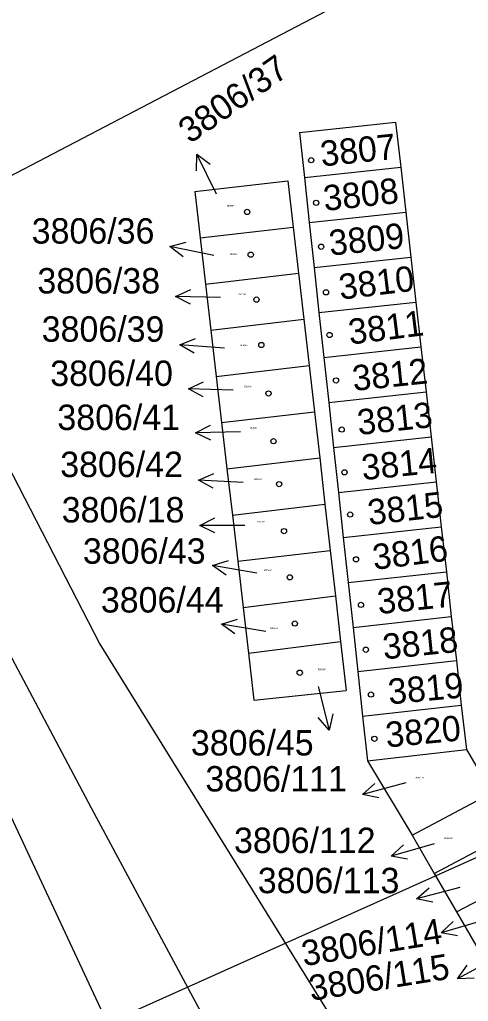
# Model space of a CAD drawing. Extents: x -735092 to -733385, y -1122435 to -1118992.
# Drawn here: x -734271.7 to -734241.7, y -1121292.4 to -1121226.6 of the extents above; entities that cross this region are included whole.
import ezdxf

# ---------------------------------------------------------------- set-up
doc = ezdxf.new("R2010")
doc.units = 0
for name, color, linetype in [('Vrstva 1', 7, 'Continuous'), ('Vrstva 10', 7, 'Continuous'), ('Vrstva 12', 7, 'Continuous'), ('Vrstva 16', 7, 'Continuous'), ('Vrstva 18', 7, 'Continuous'), ('Vrstva 19', 7, 'Continuous'), ('Vrstva 25', 7, 'Continuous')]:
    doc.layers.add(name, color=color, linetype=linetype)

msp = doc.modelspace()

# ---------------------------------------------------------------- linework, layer by layer
at = {"layer": 'Vrstva 1'}
for points in [[(-734288.89, -1121224.69), (-734266.35, -1121268.46)], [(-734252.98, -1121234.21), (-734246.54, -1121233.51)], [(-734246.54, -1121233.51), (-734246.2, -1121236.52)], [(-734252.98, -1121234.21), (-734252.65, -1121237.22)], [(-734252.65, -1121237.22), (-734246.2, -1121236.52)], [(-734246.2, -1121236.52), (-734245.86, -1121239.53)], [(-734252.65, -1121237.22), (-734252.33, -1121240.23)], [(-734259.98, -1121238.16), (-734253.75, -1121237.44)], [(-734253.75, -1121237.44), (-734253.39, -1121240.53)], [(-734259.98, -1121238.16), (-734259.62, -1121241.25)], [(-734252.33, -1121240.23), (-734245.86, -1121239.53)], [(-734245.86, -1121239.53), (-734245.52, -1121242.54)], [(-734259.62, -1121241.25), (-734253.39, -1121240.53)], [(-734253.39, -1121240.53), (-734253.04, -1121243.62)], [(-734252.33, -1121240.23), (-734252, -1121243.24)], [(-734259.62, -1121241.25), (-734259.26, -1121244.35)], [(-734252, -1121243.24), (-734245.52, -1121242.54)], [(-734245.52, -1121242.54), (-734245.18, -1121245.55)], [(-734252, -1121243.24), (-734251.67, -1121246.26)], [(-734259.26, -1121244.35), (-734253.04, -1121243.62)], [(-734253.04, -1121243.62), (-734252.68, -1121246.71)], [(-734259.26, -1121244.35), (-734258.91, -1121247.44)], [(-734251.67, -1121246.26), (-734245.18, -1121245.55)], [(-734245.18, -1121245.55), (-734244.84, -1121248.56)], [(-734251.67, -1121246.26), (-734251.35, -1121249.27)], [(-734258.91, -1121247.44), (-734252.68, -1121246.71)], [(-734252.68, -1121246.71), (-734252.33, -1121249.81)], [(-734258.91, -1121247.44), (-734258.55, -1121250.53)], [(-734251.35, -1121249.27), (-734244.84, -1121248.56)], [(-734244.84, -1121248.56), (-734244.5, -1121251.57)], [(-734258.55, -1121250.53), (-734252.33, -1121249.81)], [(-734252.33, -1121249.81), (-734251.98, -1121252.9)], [(-734251.35, -1121249.27), (-734251.02, -1121252.28)], [(-734258.55, -1121250.53), (-734258.19, -1121253.62)], [(-734251.02, -1121252.28), (-734244.5, -1121251.57)], [(-734244.5, -1121251.57), (-734244.16, -1121254.57)], [(-734251.02, -1121252.28), (-734250.69, -1121255.29)], [(-734258.19, -1121253.62), (-734251.98, -1121252.9)], [(-734251.98, -1121252.9), (-734251.62, -1121255.99)], [(-734258.19, -1121253.62), (-734257.83, -1121256.72)], [(-734250.69, -1121255.29), (-734244.16, -1121254.57)], [(-734244.16, -1121254.57), (-734243.82, -1121257.59)], [(-734250.69, -1121255.29), (-734250.37, -1121258.31)], [(-734257.83, -1121256.72), (-734251.62, -1121255.99)], [(-734251.62, -1121255.99), (-734251.27, -1121259.08)], [(-734257.83, -1121256.72), (-734257.47, -1121259.81)], [(-734250.37, -1121258.31), (-734243.82, -1121257.59)], [(-734243.82, -1121257.59), (-734243.48, -1121260.6)], [(-734250.37, -1121258.31), (-734250.04, -1121261.32)], [(-734257.47, -1121259.81), (-734251.27, -1121259.08)], [(-734251.27, -1121259.08), (-734250.92, -1121262.18)], [(-734257.47, -1121259.81), (-734257.11, -1121262.9)], [(-734250.04, -1121261.32), (-734243.48, -1121260.6)], [(-734243.48, -1121260.6), (-734243.14, -1121263.61)], [(-734250.04, -1121261.32), (-734249.71, -1121264.33)], [(-734257.11, -1121262.9), (-734250.92, -1121262.18)], [(-734250.92, -1121262.18), (-734250.57, -1121265.22)], [(-734257.11, -1121262.9), (-734256.75, -1121266)], [(-734249.71, -1121264.33), (-734243.14, -1121263.61)], [(-734243.14, -1121263.61), (-734242.81, -1121266.61)], [(-734249.71, -1121264.33), (-734249.39, -1121267.34)], [(-734256.75, -1121266), (-734250.57, -1121265.22)], [(-734250.57, -1121265.22), (-734250.22, -1121268.28)], [(-734256.75, -1121266), (-734256.4, -1121269.07)], [(-734249.39, -1121267.34), (-734242.81, -1121266.61)], [(-734242.81, -1121266.61), (-734242.47, -1121269.56)], [(-734249.39, -1121267.34), (-734249.07, -1121270.29)], [(-734266.35, -1121268.46), (-734246.74, -1121300.05)], [(-734256.4, -1121269.07), (-734250.22, -1121268.28)], [(-734250.22, -1121268.28), (-734249.84, -1121271.56)], [(-734256.4, -1121269.07), (-734256.03, -1121272.2)], [(-734249.07, -1121270.29), (-734242.47, -1121269.56)], [(-734242.47, -1121269.56), (-734242.14, -1121272.54)], [(-734249.07, -1121270.29), (-734248.75, -1121273.27)], [(-734256.03, -1121272.2), (-734249.84, -1121271.56)], [(-734248.75, -1121273.27), (-734242.14, -1121272.54)], [(-734242.14, -1121272.54), (-734241.8, -1121275.52)], [(-734248.75, -1121273.27), (-734248.42, -1121276.27)], [(-734248.42, -1121276.27), (-734241.8, -1121275.52)], [(-734241.8, -1121275.52), (-734240.09, -1121278.4)], [(-734248.42, -1121276.27), (-734245.44, -1121281.24)], [(-734245.44, -1121281.24), (-734240.09, -1121278.4)], [(-734272.61, -1121279.33), (-734227.25, -1121376.46)], [(-734245.44, -1121281.24), (-734243.95, -1121283.81)], [(-734243.95, -1121283.81), (-734238.61, -1121280.98)], [(-734243.95, -1121283.81), (-734242.46, -1121286.38)], [(-734242.46, -1121286.38), (-734237.11, -1121283.58)], [(-734242.46, -1121286.38), (-734240.92, -1121289.03)]]:
    msp.add_lwpolyline(points, dxfattribs=at)
at = {"layer": 'Vrstva 10'}
for points in [[(-734266.9, -1121279.43), (-734280.89, -1121253.09)], [(-734253.94, -1121303.58), (-734266.9, -1121279.43)]]:
    msp.add_lwpolyline(points, dxfattribs=at)
at = {"layer": 'Vrstva 12'}
for points in [[(-734359.03, -1121282.41), (-734007.75, -1121098.86)], [(-734360.81, -1121336.42), (-734230.19, -1121277.82)]]:
    msp.add_lwpolyline(points, dxfattribs=at)
at = {"layer": 'Vrstva 25'}
for points in [[(-734259.863, -1121236.76), (-734259.85, -1121235.642), (-734258.963, -1121236.323)], [(-734258.54, -1121238.34), (-734259.85, -1121235.642)], [(-734260.769, -1121242.528), (-734261.651, -1121241.843), (-734260.573, -1121241.548)], [(-734258.71, -1121242.43), (-734261.651, -1121241.843)], [(-734260.28, -1121245.704), (-734261.269, -1121245.182), (-734260.258, -1121244.705)], [(-734258.27, -1121245.25), (-734261.269, -1121245.182)], [(-734260.022, -1121248.985), (-734260.981, -1121248.41), (-734259.945, -1121247.989)], [(-734257.99, -1121248.64), (-734260.981, -1121248.41)], [(-734259.422, -1121251.897), (-734260.408, -1121251.372), (-734259.396, -1121250.898)], [(-734257.41, -1121251.45), (-734260.408, -1121251.372)], [(-734258.916, -1121254.792), (-734259.928, -1121254.318), (-734258.942, -1121253.793)], [(-734256.93, -1121254.24), (-734259.928, -1121254.318)], [(-734258.764, -1121258.021), (-734259.735, -1121257.468), (-734258.71, -1121257.023)], [(-734256.74, -1121257.63), (-734259.735, -1121257.468)], [(-734258.64, -1121261.009), (-734259.64, -1121260.51), (-734258.64, -1121260.01)], [(-734256.64, -1121260.51), (-734259.64, -1121260.51)], [(-734257.896, -1121263.845), (-734258.794, -1121263.18), (-734257.722, -1121262.861)], [(-734255.84, -1121263.7), (-734258.794, -1121263.18)], [(-734257.295, -1121267.775), (-734258.197, -1121267.115), (-734257.127, -1121266.791)], [(-734255.24, -1121267.62), (-734258.197, -1121267.115)], [(-734251.72, -1121271.3), (-734250.995, -1121274.21)], [(-734250.752, -1121273.119), (-734250.995, -1121274.21), (-734251.721, -1121273.361)], [(-734245.86, -1121277.75), (-734248.76, -1121278.516)], [(-734247.665, -1121278.744), (-734248.76, -1121278.516), (-734247.921, -1121277.777)], [(-734243.95, -1121281.83), (-734246.836, -1121282.646)], [(-734245.738, -1121282.855), (-734246.836, -1121282.646), (-734246.01, -1121281.893)], [(-734242.23, -1121284.74), (-734245.133, -1121285.496)], [(-734244.039, -1121285.727), (-734245.133, -1121285.496), (-734244.291, -1121284.76)], [(-734240.62, -1121286.93), (-734243.494, -1121287.787)], [(-734242.393, -1121287.98), (-734243.494, -1121287.787), (-734242.679, -1121287.022)], [(-734239.76, -1121289.44), (-734242.401, -1121290.862)], [(-734241.283, -1121290.828), (-734242.401, -1121290.862), (-734241.757, -1121289.947)]]:
    msp.add_lwpolyline(points, dxfattribs=at)
for centre in [(-734252.19, -1121236.06), (-734251.86, -1121238.91), (-734256.48, -1121239.52), (-734251.53, -1121241.85), (-734256.24, -1121242.38), (-734255.86, -1121245.39), (-734251.2, -1121244.9), (-734250.96, -1121247.76), (-734255.53, -1121248.43), (-734250.53, -1121250.8), (-734255.05, -1121251.67), (-734250.15, -1121254.09), (-734254.72, -1121254.87), (-734249.96, -1121256.95), (-734254.34, -1121257.74), (-734249.58, -1121259.78), (-734254.01, -1121260.89), (-734249.19, -1121262.78), (-734253.62, -1121263.98), (-734248.86, -1121265.83), (-734253.29, -1121267.08), (-734248.53, -1121268.83), (-734252.96, -1121270.37), (-734248.19, -1121271.83), (-734247.96, -1121274.79)]:
    msp.add_circle(centre, 0.175, dxfattribs=at)

# ---------------------------------------------------------------- texts
at = {"layer": 'Vrstva 16'}
for s, rotation, p in [('3806/37', 34.90028, (-734260.311, -1121234.992)), ('3806/114', 9.40008, (-734252.689, -1121290.023)), ('3806/115', 9.10007, (-734252.199, -1121292.347))]:
    msp.add_text(s, height=1.7, rotation=rotation, dxfattribs=at).set_placement(p)
for s, p in [('3806/36', (-734270.907, -1121241.64)), ('3806/38', (-734270.527, -1121244.98)), ('3806/39', (-734270.237, -1121248.21)), ('3806/40', (-734269.667, -1121251.17)), ('3806/41', (-734269.187, -1121254.12)), ('3806/42', (-734268.997, -1121257.27)), ('3806/18', (-734268.897, -1121260.31)), ('3806/43', (-734267.477, -1121263.07)), ('3806/44', (-734266.277, -1121266.34)), ('3806/45', (-734260.247, -1121275.91)), ('3806/111', (-734259.278, -1121278.32)), ('3806/112', (-734257.358, -1121282.44)), ('3806/113', (-734255.768, -1121285.13))]:
    msp.add_text(s, height=1.7, dxfattribs=at).set_placement(p)
at = {"layer": 'Vrstva 18'}
msp.add_text('3806/111', height=0.1, dxfattribs=at).set_placement((-734245.23, -1121277.44))
at = {"layer": 'Vrstva 19'}
for s, rotation, p in [('3807', 5.90005, (-734251.492, -1121236.481)), ('3808', 6.20005, (-734251.293, -1121239.46)), ('3809', 5.90005, (-734250.922, -1121242.451)), ('3810', 6.90006, (-734250.236, -1121245.398)), ('3811', 7.20006, (-734249.597, -1121248.407)), ('3812', 5.90005, (-734249.352, -1121251.511)), ('3813', 6.10005, (-734249.023, -1121254.46)), ('3814', 5.70004, (-734248.741, -1121257.482)), ('3815', 6.40005, (-734248.314, -1121260.489)), ('3816', 7.10006, (-734247.977, -1121263.487)), ('3817', 5.90005, (-734247.682, -1121266.451)), ('3818', 5.80005, (-734247.322, -1121269.481)), ('3819', 5.30004, (-734246.97, -1121272.493)), ('3820', 5.50004, (-734247.141, -1121275.382))]:
    msp.add_text(s, height=1.7, rotation=rotation, dxfattribs=at).set_placement(p)
for s, p in [('3806/37', (-734257.84, -1121239.16)), ('3806/36', (-734257.64, -1121242.4)), ('3806/38', (-734257.07, -1121245.07)), ('3806/39', (-734256.97, -1121248.5)), ('3806/40', (-734256.69, -1121251.26)), ('3806/41', (-734256.3, -1121254.03)), ('3806/42', (-734256.02, -1121257.46)), ('3806/18', (-734255.82, -1121260.31)), ('3806/43', (-734255.35, -1121263.55)), ('3806/44', (-734254.95, -1121267.44)), ('3806/45', (-734251.74, -1121270.2)), ('3806/112', (-734243.31, -1121281.5))]:
    msp.add_text(s, height=0.1, dxfattribs=at).set_placement(p)

doc.saveas('drawing.dxf')
